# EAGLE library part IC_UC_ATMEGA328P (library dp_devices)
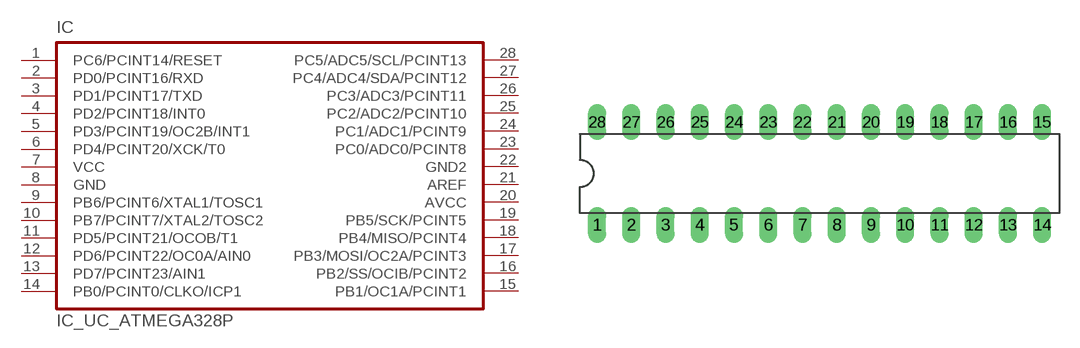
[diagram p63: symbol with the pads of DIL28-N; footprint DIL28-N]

Designator prefix IC

## IC_UC_ATMEGA328PDIL  [DIL28-N]
1  PC6/PCINT14/RESET
2  PD0/PCINT16/RXD
3  PD1/PCINT17/TXD
4  PD2/PCINT18/INT0
5  PD3/PCINT19/OC2B/INT1
6  PD4/PCINT20/XCK/T0
7  VCC
8  GND
9  PB6/PCINT6/XTAL1/TOSC1
10  PB7/PCINT7/XTAL2/TOSC2
11  PD5/PCINT21/OCOB/T1
12  PD6/PCINT22/OC0A/AIN0
13  PD7/PCINT23/AIN1
14  PB0/PCINT0/CLKO/ICP1
15  PB1/OC1A/PCINT1
16  PB2/SS/OCIB/PCINT2
17  PB3/MOSI/OC2A/PCINT3
18  PB4/MISO/PCINT4
19  PB5/SCK/PCINT5
20  AVCC
21  AREF
22  GND2
23  PC0/ADC0/PCINT8
24  PC1/ADC1/PCINT9
25  PC2/ADC2/PCINT10
26  PC3/ADC3/PCINT11
27  PC4/ADC4/SDA/PCINT12
28  PC5/ADC5/SCL/PCINT13

## Footprint DIL28-N (pad centres in mm)
drill 0.813 long: 1 -16.51,-3.81; 2 -13.97,-3.81; 3 -11.43,-3.81; 4 -8.89,-3.81; 5 -6.35,-3.81; 6 -3.81,-3.81; 7 -1.27,-3.81; 8 1.27,-3.81; 9 3.81,-3.81; 10 6.35,-3.81; 11 8.89,-3.81; 12 11.43,-3.81; 13 13.97,-3.81; 14 16.51,-3.81; 15 16.51,3.81; 16 13.97,3.81; 17 11.43,3.81; 18 8.89,3.81; 19 6.35,3.81; 20 3.81,3.81; 21 1.27,3.81; 22 -1.27,3.81; 23 -3.81,3.81; 24 -6.35,3.81; 25 -8.89,3.81; 26 -11.43,3.81; 27 -13.97,3.81; 28 -16.51,3.81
